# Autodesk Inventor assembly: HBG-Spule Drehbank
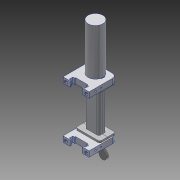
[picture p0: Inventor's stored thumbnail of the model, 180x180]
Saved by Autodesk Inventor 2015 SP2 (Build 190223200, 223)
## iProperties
Created: 2015-10
Part Number: HBG-Spule Drehbank
Document SubType Name: Assembly
Designer: rYan
Author: rYan
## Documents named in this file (6)
- D:\Tigers SVN\mechanik\2016\Inventor\Kicker\HBG-Spule Drehbank.iam
- D:\Tigers SVN\mechanik\2016\Inventor\Kicker\Spulenhalter Drehbank.ipt
- D:\Tigers SVN\mechanik\2016\Inventor\Inhaltscenter\de-DE\DIN 315\DIN 315 - M5.ipt
- D:\Tigers SVN\mechanik\2016\Inventor\Inhaltscenter\de-DE\DIN 9021\DIN 9021 - 6,4.ipt
- D:\Tigers SVN\mechanik\2016\Inventor\Kicker\MG-Spulenkoerper.iam
- D:\Tigers SVN\mechanik\2016\Inventor\Kicker\Spulenhalter.ipt
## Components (6 placed, 5 different names)
1. Spulenhalter Drehbank:1 — Passend:7, Passend:8, Passend:9, Passend:10, Passend:14, Passend:15
2. DIN 315 M5:1 — Passend:5
3. DIN 9021 6,4:1 — Passend:7, Passend:5
4. MG-Spulenkoerper:1 [sub-assembly] — Passend:11, Passend:12, Passend:13, Passend:16
5. Spulenhalter:1 — Passend:8, Passend:9, Passend:10, Passend:11, Passend:12, Passend:13
6. Spulenhalter:2 — Passend:14, Passend:15, Passend:16
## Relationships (11: Mate 11)
- Passend:5 [Mate]: DIN 315 M5:1 ↔ DIN 9021 6,4:1
- Passend:7 [Mate]: Spulenhalter Drehbank:1 ↔ DIN 9021 6,4:1
- Passend:8 [Mate]: Spulenhalter Drehbank:1 ↔ Spulenhalter:1
- Passend:9 [Mate]: Spulenhalter Drehbank:1 ↔ Spulenhalter:1
- Passend:10 [Mate]: Spulenhalter Drehbank:1 ↔ Spulenhalter:1
- Passend:11 [Mate]: MG-Spulenkoerper:1 ↔ Spulenhalter:1
- Passend:12 [Mate]: MG-Spulenkoerper:1 ↔ Spulenhalter:1
- Passend:13 [Mate]: MG-Spulenkoerper:1 ↔ Spulenhalter:1
- Passend:14 [Mate]: Spulenhalter Drehbank:1 ↔ Spulenhalter:2
- Passend:15 [Mate]: Spulenhalter Drehbank:1 ↔ Spulenhalter:2
- Passend:16 [Mate]: MG-Spulenkoerper:1 ↔ Spulenhalter:2
